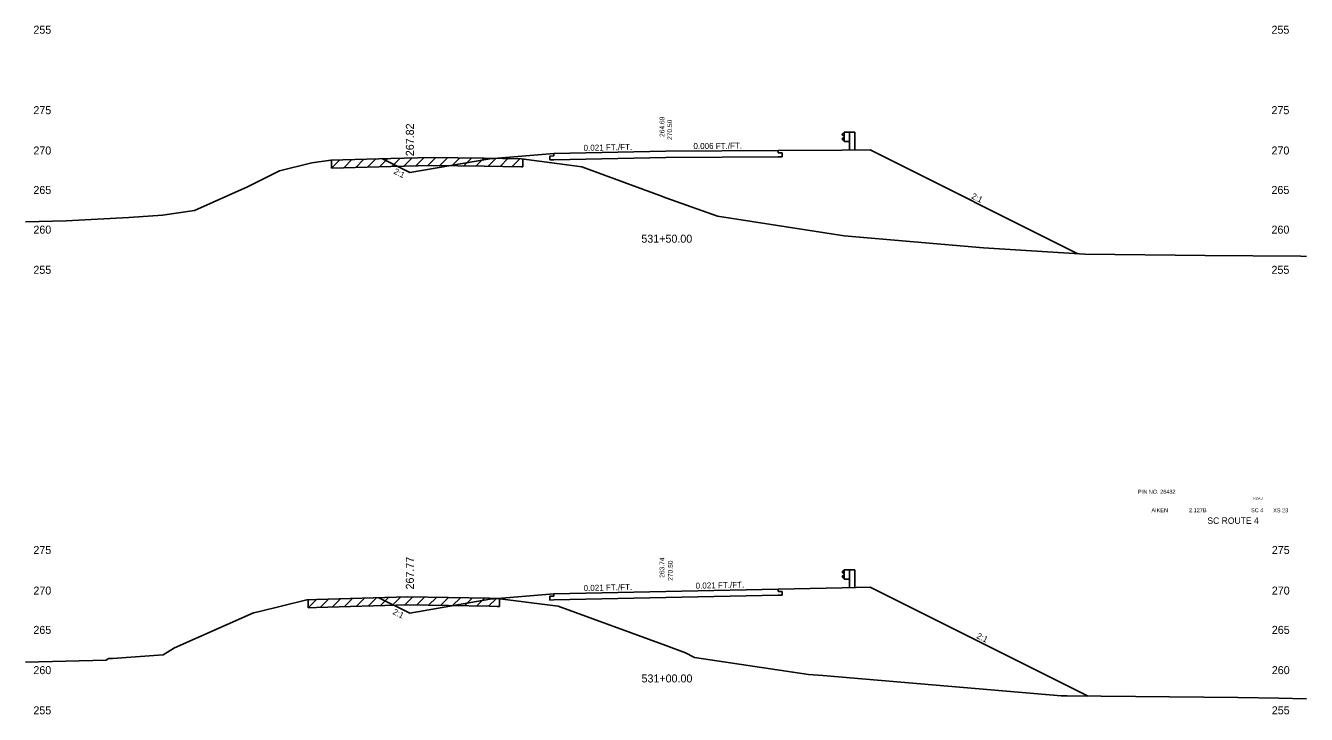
# Model space of a CAD drawing. Extents: x 883 to 1160, y 1002 to 4323.
# Drawn here: x 1000 to 1160, y 3605.1 to 3691.2 of the extents above; entities that cross this region are included whole.
import ezdxf

# ---------------------------------------------------------------- set-up
doc = ezdxf.new("R2010")
doc.units = 0
for name, color, linetype in [('Level 1', 7, 'Continuous'), ('Level 10', 7, 'Continuous'), ('Level 11', 7, 'Continuous'), ('Level 12', 7, 'Continuous'), ('Level 24', 7, 'Continuous'), ('Level 3', 7, 'Continuous'), ('Level 32', 7, 'Continuous'), ('Level 33', 7, 'Continuous'), ('Level 59', 7, 'Continuous'), ('Level 6', 7, 'Continuous'), ('Level 60', 7, 'Continuous'), ('Level 61', 7, 'Continuous'), ('Level 7', 7, 'Continuous')]:
    doc.layers.add(name, color=color, linetype=linetype)

msp = doc.modelspace()

# ---------------------------------------------------------------- linework, layer by layer
at = {"layer": 'Level 11'}
for p, q in [((1066, 3675.21), (1066, 3674.91)), ((1094, 3675.29), (1094, 3675.59)), ((1094.5, 3675.29), (1094, 3675.29)), ((1094.5, 3674.81), (1094.5, 3675.29)), ((1066, 3674.91), (1065.5, 3674.9)), ((1065.5, 3674.9), (1065.5, 3674.42)), ((1065.5, 3674.42), (1066, 3674.43)), ((1094, 3674.81), (1094.5, 3674.81)), ((1066, 3619.91), (1065.5, 3619.9)), ((1065.5, 3619.9), (1065.5, 3619.42)), ((1065.5, 3619.42), (1066, 3619.43)), ((1066, 3620.21), (1066, 3619.91)), ((1094, 3620.49), (1094, 3620.79)), ((1094.5, 3620.5), (1094, 3620.49)), ((1094, 3620.01), (1094.5, 3620.02)), ((1094.5, 3620.02), (1094.5, 3620.5))]:
    msp.add_line(p, q, dxfattribs=at)
at = {"layer": 'Level 12'}
for p, q in [((1080, 3674.72), (1066, 3674.43)), ((1094, 3674.81), (1080, 3674.72)), ((1080, 3619.72), (1066, 3619.43)), ((1094, 3620.01), (1080, 3619.72))]:
    msp.add_line(p, q, dxfattribs=at)
at = {"layer": 'Level 24'}
for p, q in [((1102.27, 3677.81), (1102, 3677.61)), ((1102, 3677.61), (1102, 3677.56)), ((1102, 3677.56), (1102.27, 3677.36)), ((1102, 3677.04), (1102.27, 3677.24)), ((1102, 3676.99), (1102, 3677.04)), ((1102.27, 3676.79), (1102, 3676.99)), ((1102.27, 3676.72), (1102.27, 3677.89)), ((1102.27, 3677.89), (1102.94, 3677.89)), ((1102.94, 3677.89), (1102.94, 3675.64)), ((1102.94, 3677.89), (1103.6, 3677.89)), ((1103.6, 3677.89), (1103.6, 3675.65)), ((1102.27, 3676.72), (1102.94, 3676.72)), ((1102.27, 3623.13), (1102, 3622.93)), ((1102, 3622.93), (1102, 3622.88)), ((1102, 3622.88), (1102.27, 3622.68)), ((1102, 3622.36), (1102.27, 3622.56)), ((1102.27, 3622.04), (1102.27, 3623.21)), ((1102.27, 3623.21), (1102.94, 3623.21)), ((1102.94, 3623.21), (1102.94, 3620.98)), ((1102.94, 3623.21), (1103.6, 3623.21)), ((1103.6, 3623.21), (1103.6, 3620.99)), ((1102, 3622.31), (1102, 3622.36)), ((1102.27, 3622.11), (1102, 3622.31)), ((1102.27, 3622.04), (1102.94, 3622.04))]:
    msp.add_line(p, q, dxfattribs=at)
at = {"layer": 'Level 59'}
for p, q in [((1066, 3675.21), (1080, 3675.5)), ((1080, 3675.5), (1094, 3675.59)), ((1066, 3620.21), (1080, 3620.5)), ((1080, 3620.5), (1094, 3620.79))]:
    msp.add_line(p, q, dxfattribs=at)
at = {"layer": 'Level 6'}
for p, q in [((1058, 3674.54), (1066, 3675.21)), ((1094, 3675.59), (1102, 3675.64)), ((1102, 3675.64), (1105.5, 3675.66)), ((1094, 3620.79), (1102, 3620.96)), ((1102, 3620.96), (1105.5, 3621.03)), ((1058, 3619.54), (1066, 3620.21))]:
    msp.add_line(p, q, dxfattribs=at)
at = {"layer": 'Level 60'}
for p, q in [((1031.7, 3673.05), (1035.75, 3674.04)), ((1035.75, 3674.04), (1038.14, 3674.4)), ((1038.14, 3674.4), (1045.64, 3674.61)), ((1045.64, 3674.61), (1050.7, 3674.73)), ((1050.7, 3674.73), (1057.28, 3674.64)), ((1057.28, 3674.64), (1061.96, 3674.55)), ((1061.96, 3674.55), (1066.37, 3673.98)), ((1066.37, 3673.98), (1069.47, 3673.53)), ((1027.71, 3671.06), (1031.7, 3673.05)), ((1069.47, 3673.53), (1079.25, 3669.96)), ((1021.08, 3668.11), (1027.71, 3671.06)), ((1079.25, 3669.96), (1080, 3669.69)), ((1080, 3669.69), (1086.44, 3667.37)), ((1005.06, 3666.82), (1012.88, 3667.21)), ((1012.88, 3667.21), (1017.12, 3667.51)), ((1017.12, 3667.51), (1021.08, 3668.11)), ((1086.44, 3667.37), (1095.02, 3666.06)), ((1000, 3666.68), (1005.06, 3666.82)), ((1095.02, 3666.06), (1102.25, 3664.94)), ((1102.25, 3664.94), (1119.68, 3663.42)), ((1119.68, 3663.42), (1132.34, 3662.63)), ((1132.34, 3662.63), (1147.35, 3662.47)), ((1147.35, 3662.47), (1159.29, 3662.37)), ((1159.29, 3662.37), (1160, 3662.36)), ((1029.04, 3617.95), (1035.12, 3619.43)), ((1035.12, 3619.43), (1036.33, 3619.47)), ((1036.33, 3619.47), (1047.72, 3619.8)), ((1047.72, 3619.8), (1057.93, 3619.65)), ((1057.93, 3619.65), (1058.92, 3619.63)), ((1058.92, 3619.63), (1065.88, 3618.73)), ((1018.58, 3613.44), (1028.48, 3617.84)), ((1028.48, 3617.84), (1029.04, 3617.95)), ((1065.88, 3618.73), (1066.53, 3618.64)), ((1066.53, 3618.64), (1080, 3613.74)), ((1017.17, 3612.58), (1018.58, 3613.44)), ((1080, 3613.74), (1082.44, 3612.84)), ((1082.44, 3612.84), (1083.54, 3612.24)), ((1000, 3611.64), (1010.06, 3611.92)), ((1010.06, 3611.92), (1010.36, 3612.13)), ((1010.36, 3612.13), (1010.87, 3612.13)), ((1010.87, 3612.13), (1017.17, 3612.58)), ((1083.54, 3612.24), (1097.79, 3610.1)), ((1097.79, 3610.1), (1099.58, 3609.99)), ((1099.58, 3609.99), (1129.35, 3607.44)), ((1129.35, 3607.44), (1130.11, 3607.44)), ((1130.11, 3607.44), (1151.45, 3607.22)), ((1151.45, 3607.22), (1156.56, 3607.16)), ((1156.56, 3607.16), (1160, 3607.08))]:
    msp.add_line(p, q, dxfattribs=at)
at = {"layer": 'Level 61'}
for p, q in [((1039.26, 3674.43), (1038.23, 3673.4)), ((1038.23, 3674.4), (1038.23, 3673.4)), ((1038.23, 3673.4), (1045.64, 3673.61)), ((1040.77, 3674.47), (1039.74, 3673.44)), ((1042.27, 3674.51), (1041.24, 3673.48)), ((1043.77, 3674.56), (1042.74, 3673.53)), ((1045.27, 3674.6), (1044.24, 3673.57)), ((1045.64, 3673.61), (1050.7, 3673.73)), ((1046.77, 3674.64), (1045.75, 3673.61)), ((1048.28, 3674.67), (1047.25, 3673.65)), ((1049.78, 3674.71), (1048.75, 3673.68)), ((1051.26, 3674.72), (1050.25, 3673.72)), ((1050.7, 3673.73), (1057.28, 3673.64)), ((1052.74, 3674.7), (1051.76, 3673.72)), ((1054.25, 3674.68), (1053.26, 3673.69)), ((1055.75, 3674.66), (1054.76, 3673.67)), ((1057.25, 3674.64), (1056.26, 3673.65)), ((1057.28, 3673.64), (1061.96, 3673.55)), ((1058.75, 3674.61), (1057.77, 3673.63)), ((1060.25, 3674.58), (1059.27, 3673.6)), ((1061.76, 3674.56), (1060.77, 3673.57)), ((1062.13, 3673.53), (1062.13, 3674.53)), ((1061.96, 3673.55), (1062.13, 3673.53)), ((1036.33, 3619.47), (1035.3, 3618.44)), ((1035.3, 3619.44), (1035.3, 3618.44)), ((1037.83, 3619.51), (1036.8, 3618.48)), ((1039.33, 3619.56), (1038.3, 3618.53)), ((1040.83, 3619.6), (1039.8, 3618.57)), ((1042.34, 3619.64), (1041.31, 3618.61)), ((1043.84, 3619.68), (1042.81, 3618.66)), ((1045.34, 3619.73), (1044.31, 3618.7)), ((1046.84, 3619.77), (1045.81, 3618.74)), ((1048.32, 3619.79), (1047.32, 3618.78)), ((1049.81, 3619.77), (1048.82, 3618.78)), ((1051.31, 3619.74), (1050.32, 3618.76)), ((1052.81, 3619.72), (1051.82, 3618.74)), ((1054.31, 3619.7), (1053.33, 3618.72)), ((1055.82, 3619.68), (1054.83, 3618.69)), ((1057.32, 3619.66), (1056.33, 3618.67)), ((1058.81, 3619.63), (1057.83, 3618.65)), ((1059.19, 3618.59), (1059.19, 3619.59)), ((1035.3, 3618.44), (1036.33, 3618.47)), ((1036.33, 3618.47), (1047.72, 3618.8)), ((1047.72, 3618.8), (1057.93, 3618.65)), ((1057.93, 3618.65), (1058.92, 3618.63)), ((1058.92, 3618.63), (1059.19, 3618.59))]:
    msp.add_line(p, q, dxfattribs=at)
at = {"layer": 'Level 7'}
for p, q in [((1105.5, 3675.66), (1131.45, 3662.68)), ((1044.48, 3674.58), (1048, 3672.82)), ((1048, 3672.82), (1058, 3674.54)), ((1105.5, 3621.03), (1132.74, 3607.41)), ((1044.14, 3619.69), (1048, 3617.77)), ((1048, 3617.77), (1058, 3619.54))]:
    msp.add_line(p, q, dxfattribs=at)

# ---------------------------------------------------------------- texts
at = {"layer": 'Level 1'}
for s, height, p in [('531+50.00', 1, (1076.92, 3664.07)), ('PIN NO. 26432', 0.5, (1138.97, 3632.7)), ('AIKEN', 0.5, (1140.64, 3630.39)), (' 2.127B', 0.5, (1145.15, 3630.39)), ('SC 4', 0.5, (1153.09, 3630.39)), ('XS 23', 0.5, (1155.85, 3630.38)), ('SC ROUTE 4', 0.8, (1147.63, 3628.94)), ('531+00.00', 1, (1076.94, 3609.12))]:
    msp.add_text(s, height=height, dxfattribs=at).set_placement(p)
at = {"layer": 'Level 10'}
for s, p in [('264.69', (1079.8, 3677.28)), ('263.74', (1079.8, 3622.2))]:
    msp.add_text(s, height=0.6, rotation=90, dxfattribs=at).set_placement(p)
at = {"layer": 'Level 3'}
for s, height, p in [(' 255', 1, (1000.6, 3690.18)), (' 255', 1, (1155.27, 3690.18)), (' 275', 1, (1000.6, 3680.13)), (' 275', 1, (1155.27, 3680.13)), (' 270', 1, (1000.6, 3675.09)), (' 270', 1, (1155.27, 3675.09)), (' 265', 1, (1000.6, 3670.16)), (' 265', 1, (1155.27, 3670.16)), (' 260', 1, (1000.6, 3665.2)), (' 260', 1, (1155.27, 3665.2)), (' 255', 1, (1000.6, 3660.18)), (' 255', 1, (1155.27, 3660.18)), ('ROAD', 0.3, (1153.38, 3631.97)), (' 275', 1, (1000.6, 3625.17)), (' 275', 1, (1155.31, 3625.17)), (' 270', 1, (1000.6, 3620.1)), (' 270', 1, (1155.31, 3620.1)), (' 265', 1, (1000.6, 3615.19)), (' 265', 1, (1155.31, 3615.19)), (' 260', 1, (1000.6, 3610.16)), (' 260', 1, (1155.31, 3610.16)), (' 255', 1, (1000.6, 3605.14)), (' 255', 1, (1155.31, 3605.14))]:
    msp.add_text(s, height=height, dxfattribs=at).set_placement(p)
at = {"layer": 'Level 32'}
for s, rotation, p in [('0.021 FT./FT.', 1.1916, (1069.71, 3675.54)), ('0.006 FT./FT.', 0.356, (1083.43, 3675.77)), ('2:1', 333.435, (1045.9, 3672.74)), ('2:1', 333.435, (1118.08, 3669.65)), ('0.021 FT./FT.', 1.1916, (1069.71, 3620.54)), ('0.021 FT./FT.', 1.1916, (1083.71, 3620.83)), ('2:1', 333.435, (1045.78, 3617.7)), ('2:1', 333.435, (1118.73, 3614.7))]:
    msp.add_text(s, height=0.75, rotation=rotation, dxfattribs=at).set_placement(p)
at = {"layer": 'Level 33'}
for s, p in [('267.82', (1048.5, 3674.88)), ('267.77', (1048.5, 3620.74))]:
    msp.add_text(s, height=1, rotation=90, dxfattribs=at).set_placement(p)
at = {"layer": 'Level 59'}
for p in [(1080.76, 3676.68), (1080.85, 3621.59)]:
    msp.add_text(' 270.50', height=0.6, rotation=90, dxfattribs=at).set_placement(p)

doc.saveas('drawing.dxf')
